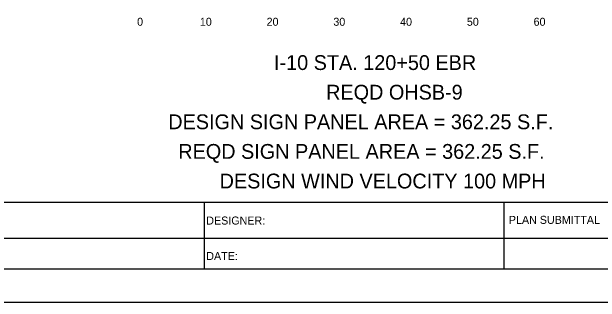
# Model space of a CAD drawing. Extents: x 1797809 to 2198143, y 249608 to 1237864.
# Drawn here: x 2195638.5 to 2195726.7, y 1237118 to 1237161.6 of the extents above; entities that cross this region are included whole.
import ezdxf

# ---------------------------------------------------------------- set-up
doc = ezdxf.new("R2010")
doc.units = 0
for name, color, linetype in [('10', 7, 'Continuous'), ('GSCOLORFILL', 7, 'Continuous'), ('GSOUTLINE', 7, 'Continuous'), ('GSSHT', 7, 'Continuous'), ('Level 45', 7, 'Continuous'), ('Level 55', 7, 'Continuous')]:
    doc.layers.add(name, color=color, linetype=linetype)

msp = doc.modelspace()

# ---------------------------------------------------------------- linework, layer by layer
at = {"layer": 'GSCOLORFILL'}
for p, q in [((2195667.371, 1237123.036), (2195667.371, 1237133.046)), ((2195712.296, 1237123.036), (2195712.296, 1237133.046)), ((2195574.707, 1237127.646), (2195730.334, 1237127.646))]:
    msp.add_line(p, q, dxfattribs=at)
msp.add_lwpolyline([(2195562.21, 1237123.036), (2195884.71, 1237123.036), (2195884.71, 1237333.036), (2195562.21, 1237333.036)], close=True, dxfattribs=at)
at = {"layer": 'GSSHT'}
msp.add_lwpolyline([(2195549.71, 1237118.036), (2195889.71, 1237118.036), (2195889.71, 1237338.036), (2195549.71, 1237338.036)], close=True, dxfattribs=at)
at = {"layer": 'Level 45'}
msp.add_lwpolyline([(2195574.707, 1237133.046), (2195874.707, 1237133.046), (2195874.707, 1237323.046), (2195574.707, 1237323.046)], close=True, dxfattribs=at)

# ---------------------------------------------------------------- texts
at = {"layer": '10'}
for s, p in [('0', (2195657.287, 1237159.506)), ('10', (2195666.687, 1237159.506)), ('20', (2195676.687, 1237159.506)), ('30', (2195686.687, 1237159.506)), ('40', (2195696.687, 1237159.506)), ('50', (2195706.687, 1237159.506)), ('60', (2195716.687, 1237159.506))]:
    msp.add_text(s, height=1.2, dxfattribs=at).set_placement(p)
at = {"layer": 'GSOUTLINE'}
for s, p in [('DESIGNER:', (2195667.649, 1237129.69)), ('PLAN SUBMITTAL', (2195712.981, 1237129.795)), ('DATE:', (2195667.649, 1237124.371))]:
    msp.add_text(s, height=1.2, rotation=360, dxfattribs=at).set_placement(p)
at = {"layer": 'Level 55'}
for s, p in [('I-10 STA. 120+50 EBR', (2195677.795, 1237152.873)), ('REQD OHSB-9', (2195685.601, 1237148.431)), ('DESIGN SIGN PANEL AREA = 362.25 S.F.', (2195661.955, 1237143.989)), ('REQD SIGN PANEL AREA = 362.25 S.F.', (2195663.453, 1237139.547)), ('DESIGN WIND VELOCITY 100 MPH', (2195669.648, 1237135.106))]:
    msp.add_text(s, height=2.22092, dxfattribs=at).set_placement(p)

doc.saveas('drawing.dxf')
